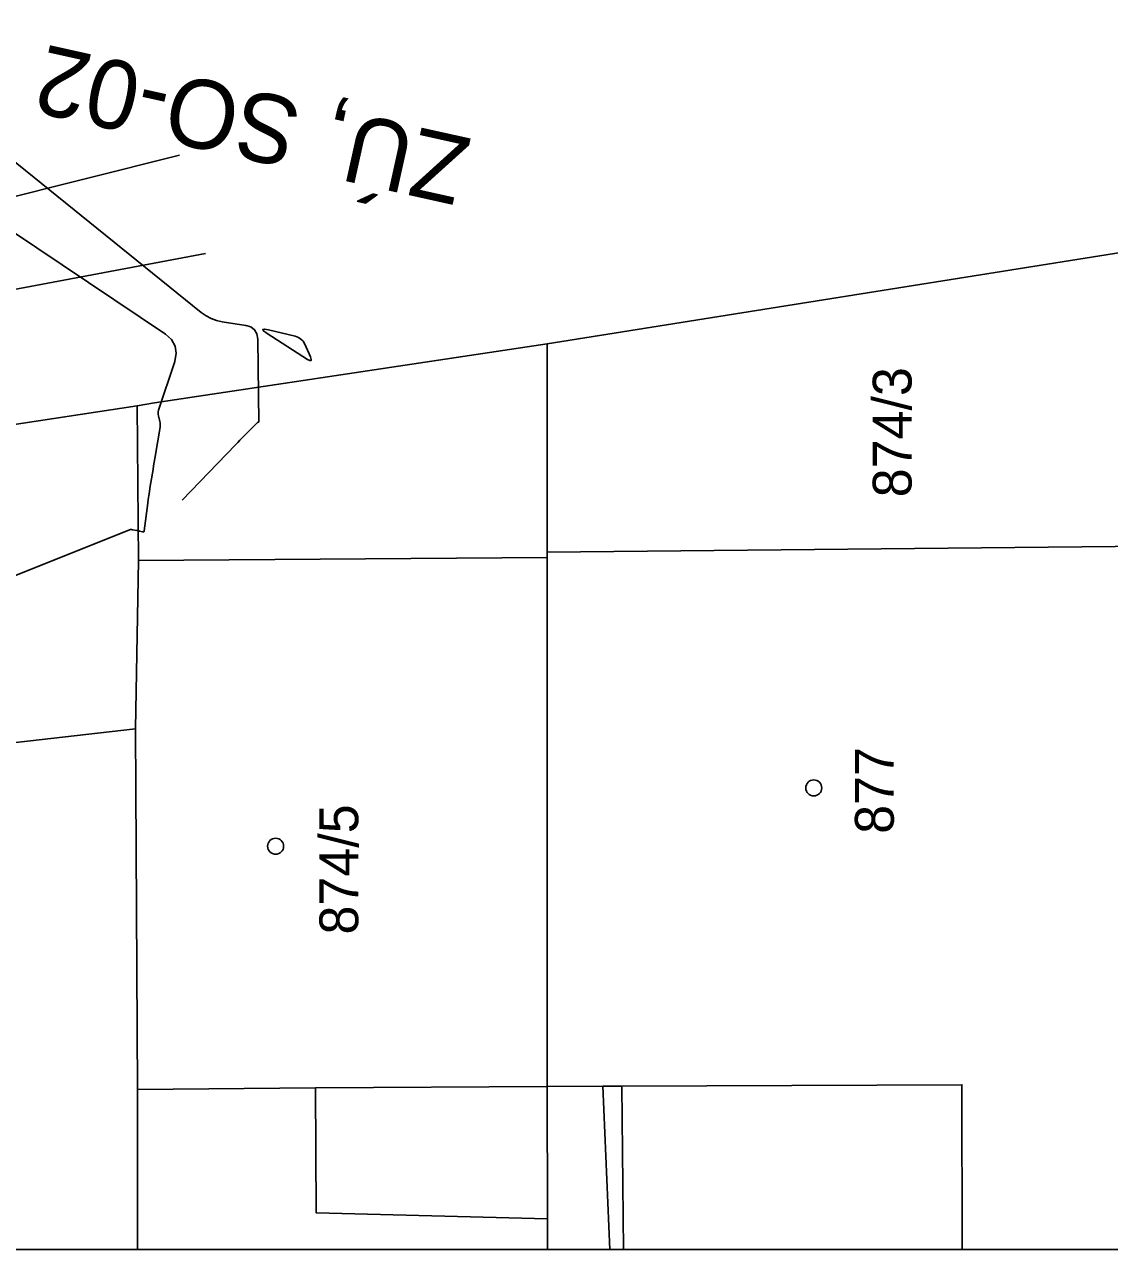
# Model space of a CAD drawing. Extents: x -534410 to -534262, y -1190162 to -1189584.
# Drawn here: x -534319.81 to -534296.08, y -1190161.97 to -1190135.2 of the extents above; entities that cross this region are included whole.
import ezdxf

# ---------------------------------------------------------------- set-up
doc = ezdxf.new("R2010")
doc.units = 0
for name, color, linetype in [('31', 7, 'Continuous'), ('_N_text', 7, 'Continuous'), ('_rámeček', 7, 'Continuous'), ('_rámeček_mřížka', 7, 'Continuous'), ('_tenka', 7, 'Continuous'), ('Hranice parcel', 7, 'Continuous'), ('Parcelní čísla', 7, 'Continuous'), ('Polygon budovy', 7, 'Continuous'), ('Značky budov', 7, 'Continuous')]:
    doc.layers.add(name, color=color, linetype=linetype)

msp = doc.modelspace()

# ---------------------------------------------------------------- linework, layer by layer
at = {"layer": '31'}
for points in [[(-534321.888, -1190136.698), (-534315.946, -1190141.494), (-534315.841, -1190141.568), (-534315.729, -1190141.627), (-534315.611, -1190141.67), (-534315.486, -1190141.697), (-534314.971, -1190141.776), (-534314.858, -1190141.809), (-534314.777, -1190141.87), (-534314.728, -1190141.959), (-534314.71, -1190142.075), (-534314.687, -1190143.886), (-534314.687, -1190143.888), (-534314.688, -1190143.89), (-534314.69, -1190143.891), (-534314.692, -1190143.891), (-534314.703, -1190143.891), (-534314.706, -1190143.891), (-534314.709, -1190143.892), (-534314.711, -1190143.893), (-534314.713, -1190143.895), (-534315.002, -1190144.184), (-534315.051, -1190144.233), (-534315.099, -1190144.282), (-534315.147, -1190144.332), (-534315.195, -1190144.381), (-534316.361, -1190145.594)], [(-534322.078, -1190148.065), (-534317.532, -1190146.248), (-534317.512, -1190146.241), (-534317.492, -1190146.238), (-534317.471, -1190146.237), (-534317.45, -1190146.239), (-534317.357, -1190146.253), (-534317.34, -1190146.256), (-534317.324, -1190146.26), (-534317.308, -1190146.264), (-534317.292, -1190146.268), (-534317.228, -1190146.287), (-534317.213, -1190146.289), (-534317.202, -1190146.286), (-534317.195, -1190146.278), (-534317.191, -1190146.264), (-534317.114, -1190145.657), (-534317.103, -1190145.576), (-534317.092, -1190145.494), (-534317.08, -1190145.413), (-534317.067, -1190145.332), (-534317.014, -1190145.007), (-534317, -1190144.926), (-534316.987, -1190144.845), (-534316.974, -1190144.763), (-534316.96, -1190144.682), (-534316.847, -1190144.001), (-534316.843, -1190143.969), (-534316.843, -1190143.938), (-534316.846, -1190143.907), (-534316.852, -1190143.876), (-534316.882, -1190143.752), (-534316.887, -1190143.721), (-534316.888, -1190143.691), (-534316.885, -1190143.66), (-534316.877, -1190143.63), (-534316.525, -1190142.563), (-534316.491, -1190142.384), (-534316.514, -1190142.225), (-534316.594, -1190142.086), (-534316.73, -1190141.966), (-534321.806, -1190138.563)]]:
    msp.add_lwpolyline(points, dxfattribs=at)
msp.add_lwpolyline([(-534313.54, -1190142.516), (-534313.545, -1190142.544), (-534313.573, -1190142.545), (-534313.625, -1190142.517), (-534314.504, -1190141.95), (-534314.581, -1190141.895), (-534314.601, -1190141.863), (-534314.564, -1190141.856), (-534314.471, -1190141.873), (-534313.89, -1190142.012), (-534313.822, -1190142.036), (-534313.765, -1190142.073), (-534313.718, -1190142.122), (-534313.682, -1190142.185), (-534313.559, -1190142.461)], close=True, dxfattribs=at)
at = {"layer": '_rámeček'}
msp.add_lwpolyline([(-534410.126, -1190161.97), (-534261.626, -1190161.97), (-534261.626, -1189584.47)], dxfattribs=at)
at = {"layer": '_rámeček_mřížka'}
msp.add_lwpolyline([(-534410.126, -1190161.97), (-534261.626, -1190161.97), (-534261.626, -1189584.47)], dxfattribs=at)
at = {"layer": '_tenka'}
for points in [[(-534344.053, -1190143.233), (-534334.908, -1190142.684), (-534316.418, -1190138.053)], [(-534345.413, -1190144.601), (-534330.814, -1190143.012), (-534315.851, -1190140.2)]]:
    msp.add_lwpolyline(points, dxfattribs=at)
at = {"layer": 'Hranice parcel'}
for p, q in [((-534308.38, -1190142.18), (-534294.84, -1190140.02)), ((-534308.38, -1190142.18), (-534308.38, -1190146.73)), ((-534317.35, -1190143.53), (-534325.64, -1190144.79)), ((-534317.34, -1190158.47), (-534317.38, -1190150.59)), ((-534317.338, -1190161.97), (-534317.34, -1190158.47)), ((-534308.38, -1190158.41), (-534307.16, -1190158.4)), ((-534308.37, -1190161.3), (-534308.38, -1190158.41)), ((-534307.16, -1190158.4), (-534307.013, -1190161.97)), ((-534308.37, -1190161.97), (-534308.37, -1190161.3))]:
    msp.add_line(p, q, dxfattribs=at)
for points in [[(-534308.38, -1190142.18), (-534316.97, -1190143.47), (-534317.35, -1190143.53)], [(-534317.35, -1190143.53), (-534317.32, -1190146.91), (-534317.38, -1190150.59)], [(-534317.38, -1190150.59), (-534324.22, -1190151.37), (-534325.64, -1190144.79)], [(-534308.38, -1190146.73), (-534295.23, -1190146.6), (-534295.23, -1190148.36)], [(-534308.38, -1190158.41), (-534308.38, -1190146.85), (-534308.38, -1190146.73)], [(-534308.37, -1190161.3), (-534313.43, -1190161.17), (-534313.45, -1190158.44), (-534317.34, -1190158.47)], [(-534307.16, -1190158.4), (-534306.75, -1190158.4), (-534306.71, -1190161.97)]]:
    msp.add_lwpolyline(points, dxfattribs=at)
at = {"layer": 'Polygon budovy'}
msp.add_line((-534299.302, -1190161.97), (-534295.233, -1190161.97), dxfattribs=at)
msp.add_lwpolyline([(-534295.233, -1190161.97), (-534295.22, -1190157.63), (-534295.23, -1190148.36), (-534295.23, -1190146.6), (-534308.38, -1190146.73), (-534308.38, -1190146.85), (-534308.38, -1190158.41), (-534307.16, -1190158.4), (-534306.75, -1190158.4), (-534299.31, -1190158.37), (-534299.302, -1190161.97)], dxfattribs=at)
msp.add_lwpolyline([(-534317.38, -1190150.59), (-534317.34, -1190158.47), (-534313.45, -1190158.44), (-534308.38, -1190158.41), (-534308.38, -1190146.85), (-534317.32, -1190146.91)], close=True, dxfattribs=at)
at = {"layer": 'Značky budov'}
for centre in [(-534302.551, -1190151.883), (-534314.318, -1190153.157)]:
    msp.add_circle(centre, 0.175, dxfattribs=at)

# ---------------------------------------------------------------- texts
at = {"layer": '_N_text'}
msp.add_text('ZÚ, SO-02', height=1.5, rotation=167.5017, dxfattribs=at).set_placement((-534309.992, -1190137.704))
at = {"layer": 'Parcelní čísla'}
for s, p in [('874/3', (-534300.411, -1190145.531)), ('877', (-534300.8, -1190152.885)), ('874/5', (-534312.511, -1190155.086))]:
    msp.add_text(s, height=0.85, rotation=90, dxfattribs=at).set_placement(p)

doc.saveas('drawing.dxf')
